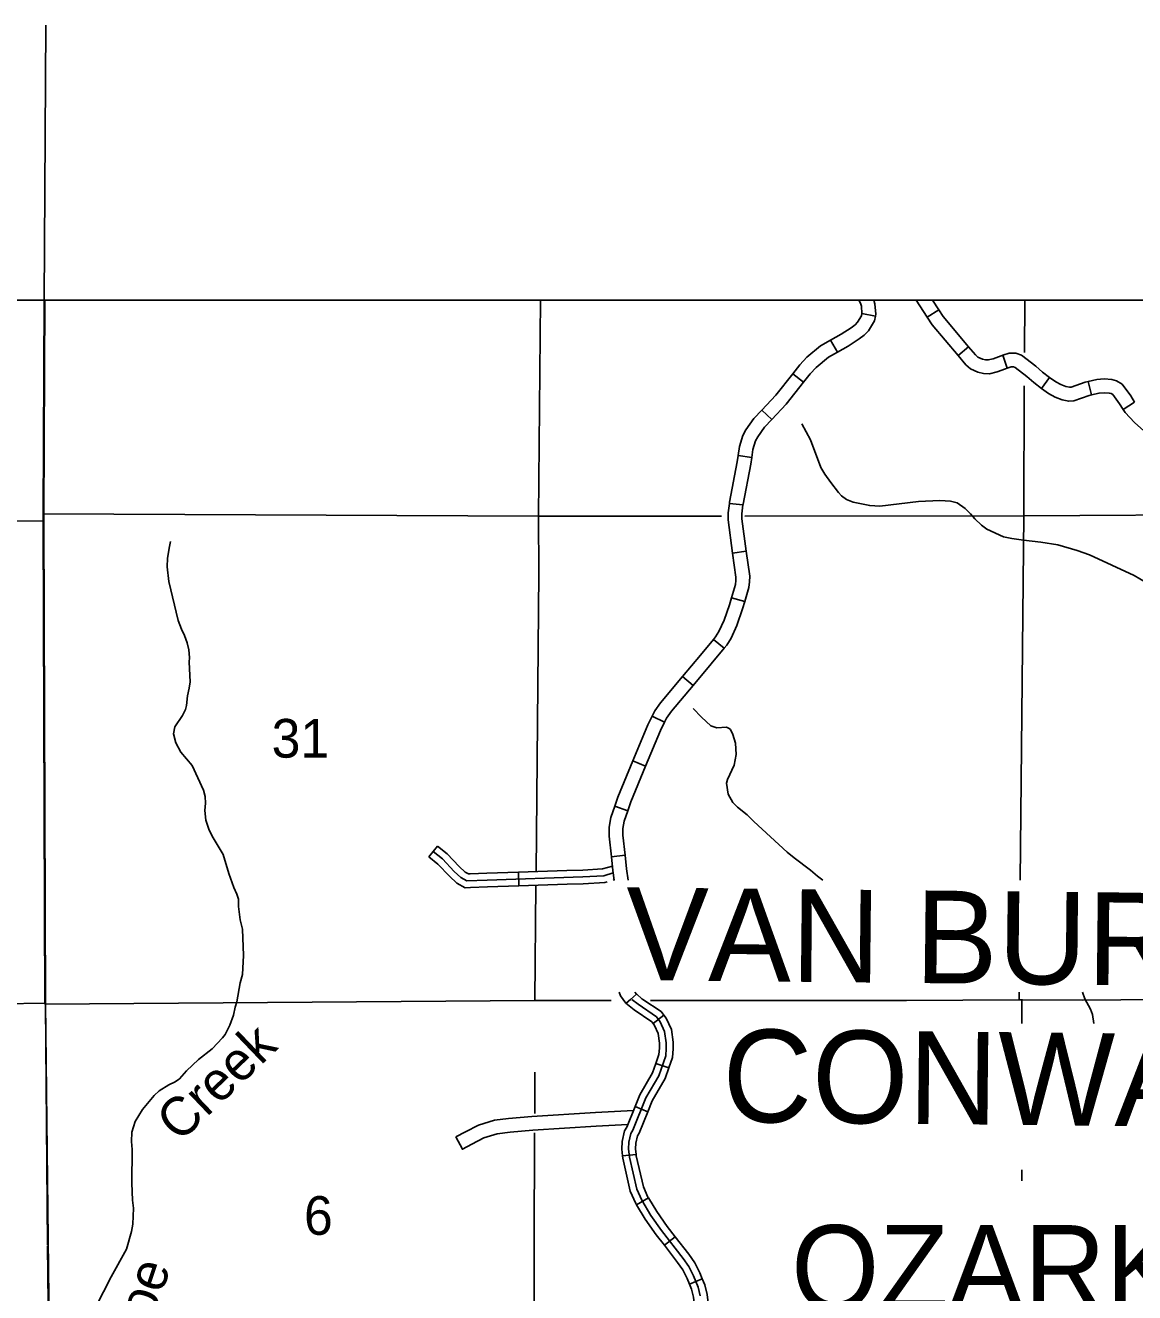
# Model space of a CAD drawing. Extents: x 1373862 to 1376999, y 1168398 to 1170455.
# Drawn here: x 1375555 to 1375797.1, y 1169362.9 to 1169639.4 of the extents above; entities that cross this region are included whole.
import ezdxf

# ---------------------------------------------------------------- set-up
doc = ezdxf.new("R2010")
doc.units = 0
for name, color, linetype in [('Level 2', 7, 'Continuous'), ('Level 32', 7, 'Continuous'), ('Level 35', 7, 'Continuous'), ('Level 4', 7, 'Continuous'), ('Level 45', 7, 'Continuous'), ('Level 46', 7, 'Continuous'), ('Level 5', 7, 'Continuous'), ('Level 8', 7, 'Continuous'), ('R_Dimension', 7, 'Continuous'), ('R_Draft', 7, 'Continuous')]:
    doc.layers.add(name, color=color, linetype=linetype)

msp = doc.modelspace()

# ---------------------------------------------------------------- linework, layer by layer
at = {"layer": 'Level 2'}
for points in [[(1375559.08, 1169579.43), (1375558.86, 1169532.82), (1375558.86, 1169531.1), (1375559.25, 1169425.84)], [(1375559.23, 1169579.43), (1375559.01, 1169532.99), (1375559, 1169531.27), (1375559.39, 1169426.01)], [(1375691.41, 1169426.65), (1375747.28, 1169426.64), (1375771.86, 1169426.75), (1375772.49, 1169426.76), (1375785.76, 1169426.72), (1375877.01, 1169427.47), (1375877.33, 1169427.47), (1375888.65, 1169427.27)], [(1375691.41, 1169426.65), (1375747.28, 1169426.64), (1375771.86, 1169426.75), (1375772.49, 1169426.76), (1375785.76, 1169426.72), (1375877.01, 1169427.47), (1375877.33, 1169427.47), (1375888.65, 1169427.27)], [(1375559.25, 1169425.84), (1375666.19, 1169426.66), (1375682.85, 1169426.66)], [(1375559.25, 1169425.84), (1375666.19, 1169426.66), (1375682.85, 1169426.66)], [(1375559.37, 1169425.84), (1375559.85, 1169373.34)], [(1375559.39, 1169426.01), (1375560.53, 1169323.17), (1375560.52, 1169321.29), (1375560.75, 1169303.22)], [(1375559.85, 1169373.12), (1375560.43, 1169323.13), (1375560.44, 1169321.15), (1375560.68, 1169300.07)]]:
    msp.add_lwpolyline(points, dxfattribs=at)
at = {"layer": 'Level 32'}
for p, q in [((1375751.81, 1169575.71), (1375754.32, 1169577.35)), ((1375737.56, 1169576.54), (1375740.5, 1169575.97)), ((1375730.69, 1169570.7), (1375732.18, 1169568.09)), ((1375758.54, 1169567.36), (1375760.83, 1169569.29)), ((1375769.21, 1169564.59), (1375768.3, 1169567.45)), ((1375722.44, 1169563.39), (1375724.8, 1169561.53)), ((1375776.7, 1169560.21), (1375778.49, 1169562.61)), ((1375787.64, 1169558.77), (1375786.94, 1169561.68)), ((1375715.68, 1169555.47), (1375717.85, 1169553.41)), ((1375794.53, 1169555.6), (1375797.06, 1169557.21)), ((1375710.52, 1169545.54), (1375713.49, 1169545.11)), ((1375708.62, 1169535.11), (1375711.59, 1169534.76)), ((1375709.33, 1169524.26), (1375712.31, 1169524.67)), ((1375709.08, 1169514.49), (1375711.97, 1169513.66)), ((1375705.16, 1169505.41), (1375707.48, 1169503.5)), ((1375698.41, 1169497.31), (1375700.7, 1169495.38)), ((1375691.77, 1169488.68), (1375694.47, 1169487.37)), ((1375687.58, 1169478.9), (1375690.35, 1169477.75)), ((1375683.61, 1169469.03), (1375686.44, 1169468.03)), ((1375682.88, 1169458.01), (1375685.86, 1169458.33)), ((1375687.02, 1169426.84), (1375688.38, 1169427.97)), ((1375686.08, 1169426.05), (1375687.02, 1169426.84)), ((1375691.98, 1169421.57), (1375694.35, 1169423.41)), ((1375692.59, 1169412.9), (1375695.42, 1169411.9)), ((1375688.03, 1169403.49), (1375690.81, 1169402.36)), ((1375685.29, 1169392.76), (1375688.28, 1169393.05)), ((1375688.38, 1169382.04), (1375690.94, 1169383.59)), ((1375694.45, 1169373.2), (1375696.82, 1169375.04)), ((1375699.94, 1169364.71), (1375702.71, 1169365.86))]:
    msp.add_line(p, q, dxfattribs=at)
for points in [[(1375736.88, 1169579.43), (1375737.21, 1169578.81), (1375737.42, 1169578.11), (1375737.56, 1169576.56), (1375737.56, 1169576.54)], [(1375740.16, 1169579.43), (1375740.38, 1169578.68), (1375740.59, 1169576.41), (1375740.5, 1169575.97)], [(1375749.37, 1169579.43), (1375751.81, 1169575.71)], [(1375752.96, 1169579.43), (1375754.32, 1169577.35)], [(1375754.32, 1169577.35), (1375755.28, 1169575.89), (1375760.83, 1169569.29)], [(1375737.56, 1169576.54), (1375737.46, 1169576.04), (1375736.6, 1169574.62), (1375736.08, 1169574.09), (1375735.21, 1169573.44), (1375732.98, 1169572.01), (1375730.69, 1169570.7)], [(1375740.5, 1169575.97), (1375740.3, 1169574.95), (1375738.98, 1169572.77), (1375738.06, 1169571.83), (1375736.93, 1169570.98), (1375734.54, 1169569.44), (1375732.18, 1169568.09)], [(1375751.81, 1169575.71), (1375752.87, 1169574.1), (1375758.54, 1169567.36)], [(1375730.69, 1169570.7), (1375728.52, 1169569.46), (1375725.5, 1169566.98), (1375723.98, 1169565.35), (1375722.44, 1169563.39)], [(1375760.83, 1169569.29), (1375762.34, 1169567.49), (1375762.87, 1169567.05), (1375763.84, 1169566.61), (1375764.52, 1169566.45), (1375765.1, 1169566.41), (1375766.15, 1169566.67), (1375767.92, 1169567.33), (1375768.3, 1169567.45)], [(1375732.18, 1169568.09), (1375730.23, 1169566.98), (1375727.56, 1169564.79), (1375726.26, 1169563.4), (1375724.8, 1169561.53)], [(1375758.54, 1169567.36), (1375760.22, 1169565.36), (1375761.26, 1169564.49), (1375762.85, 1169563.76), (1375764.08, 1169563.46), (1375765.38, 1169563.39), (1375767.03, 1169563.8), (1375768.9, 1169564.49), (1375769.21, 1169564.59)], [(1375768.3, 1169567.45), (1375769.69, 1169567.89), (1375771.16, 1169567.88), (1375772.39, 1169567.46), (1375775.49, 1169565.07), (1375776.93, 1169563.77), (1375778.49, 1169562.61)], [(1375722.44, 1169563.39), (1375718.75, 1169558.71), (1375715.68, 1169555.47)], [(1375769.21, 1169564.59), (1375770.14, 1169564.89), (1375770.65, 1169564.88), (1375770.96, 1169564.78), (1375773.56, 1169562.77), (1375775.03, 1169561.45), (1375776.7, 1169560.21)], [(1375724.8, 1169561.53), (1375721.02, 1169556.75), (1375717.85, 1169553.41)], [(1375776.7, 1169560.21), (1375778.24, 1169559.06), (1375779.69, 1169558.3), (1375781.21, 1169557.71), (1375782.69, 1169557.41), (1375783.8, 1169557.52), (1375787.12, 1169558.64), (1375787.64, 1169558.77)], [(1375778.49, 1169562.61), (1375779.85, 1169561.6), (1375780.93, 1169561.03), (1375782.05, 1169560.6), (1375782.85, 1169560.44), (1375783.17, 1169560.47), (1375786.28, 1169561.53), (1375786.94, 1169561.68)], [(1375786.94, 1169561.68), (1375788.8, 1169562.13), (1375790.37, 1169562.26), (1375792.05, 1169562.16), (1375793.13, 1169561.82), (1375794.32, 1169561.14), (1375796.21, 1169558.55), (1375797.06, 1169557.21)], [(1375787.64, 1169558.77), (1375789.28, 1169559.16), (1375790.4, 1169559.26), (1375791.5, 1169559.19), (1375791.93, 1169559.05), (1375792.28, 1169558.85), (1375793.73, 1169556.86), (1375794.53, 1169555.6)], [(1375715.68, 1169555.47), (1375713.93, 1169553.64), (1375712.24, 1169551.18), (1375711.56, 1169549.92), (1375710.8, 1169547.52), (1375710.52, 1169545.54)], [(1375794.53, 1169555.6), (1375794.96, 1169554.92), (1375797.02, 1169552.74), (1375799.04, 1169550.97), (1375800.09, 1169550.26), (1375802.16, 1169549.15), (1375803.59, 1169548.71)], [(1375717.85, 1169553.41), (1375716.27, 1169551.75), (1375714.8, 1169549.62), (1375714.34, 1169548.75), (1375713.74, 1169546.85), (1375713.49, 1169545.11)], [(1375710.52, 1169545.54), (1375710.32, 1169544.16), (1375708.65, 1169535.37), (1375708.62, 1169535.11)], [(1375713.49, 1169545.11), (1375713.28, 1169543.67), (1375711.61, 1169534.91), (1375711.59, 1169534.76)], [(1375708.62, 1169535.11), (1375708.37, 1169533.06), (1375708.34, 1169531.53), (1375709.33, 1169524.26)], [(1375711.59, 1169534.76), (1375711.37, 1169532.85), (1375711.34, 1169531.7), (1375712.31, 1169524.67)], [(1375709.33, 1169524.26), (1375710.05, 1169519.02), (1375710.04, 1169518.25), (1375709.92, 1169517.42), (1375709.08, 1169514.49)], [(1375712.31, 1169524.67), (1375713.05, 1169519.21), (1375713.04, 1169518.01), (1375712.86, 1169516.78), (1375711.97, 1169513.66)], [(1375709.08, 1169514.49), (1375708.65, 1169512.99), (1375707.48, 1169509.59), (1375706.35, 1169507.13), (1375705.62, 1169505.96), (1375705.16, 1169505.41)], [(1375711.97, 1169513.66), (1375711.51, 1169512.08), (1375710.26, 1169508.47), (1375708.99, 1169505.7), (1375708.06, 1169504.2), (1375707.48, 1169503.5)], [(1375705.16, 1169505.41), (1375702.33, 1169501.98), (1375698.41, 1169497.31)], [(1375707.48, 1169503.5), (1375704.64, 1169500.06), (1375700.7, 1169495.38)], [(1375698.41, 1169497.31), (1375693.61, 1169491.61), (1375692.32, 1169489.81), (1375691.77, 1169488.68)], [(1375700.7, 1169495.38), (1375695.98, 1169489.77), (1375694.9, 1169488.27), (1375694.47, 1169487.37)], [(1375691.77, 1169488.68), (1375690.84, 1169486.78), (1375687.58, 1169478.9)], [(1375694.47, 1169487.37), (1375693.58, 1169485.55), (1375690.35, 1169477.75)], [(1375687.58, 1169478.9), (1375684.31, 1169471.02), (1375683.61, 1169469.03)], [(1375690.35, 1169477.75), (1375687.12, 1169469.95), (1375686.44, 1169468.03)], [(1375683.61, 1169469.03), (1375682.73, 1169466.54), (1375682.39, 1169464.42), (1375682.4, 1169462.52), (1375682.88, 1169458.01)], [(1375686.44, 1169468.03), (1375685.65, 1169465.79), (1375685.39, 1169464.19), (1375685.4, 1169462.69), (1375685.86, 1169458.33)], [(1375682.88, 1169458.01), (1375683.2, 1169454.99)], [(1375685.86, 1169458.33), (1375686.18, 1169455.35), (1375686.51, 1169452.89)], [(1375683.2, 1169454.99), (1375683.48, 1169452.89)], [(1375684.56, 1169428.47), (1375684.86, 1169427.63), (1375685.43, 1169426.82)], [(1375687.96, 1169428.47), (1375688.38, 1169427.97)], [(1375688.39, 1169427.98), (1375689.55, 1169426.98), (1375689.75, 1169426.84)], [(1375691.98, 1169421.57), (1375691.67, 1169421.97), (1375687.82, 1169424.6), (1375686.05, 1169426.07), (1375685.43, 1169426.81)], [(1375686.08, 1169426.05), (1375686.05, 1169426.07), (1375685.43, 1169426.81)], [(1375694.82, 1169416.16), (1375694.85, 1169417.4), (1375694.49, 1169419.87), (1375693.55, 1169421.96), (1375692.69, 1169423.06), (1375688.68, 1169425.79), (1375687.33, 1169426.84)], [(1375694.35, 1169423.41), (1375693.75, 1169424.19), (1375689.73, 1169426.84)], [(1375695.42, 1169411.9), (1375696.23, 1169414.21), (1375696.35, 1169416.1), (1375696.38, 1169417.5), (1375695.97, 1169420.3), (1375694.86, 1169422.76), (1375694.35, 1169423.41)], [(1375692.59, 1169412.9), (1375693.26, 1169414.81), (1375693.35, 1169416.22), (1375693.37, 1169417.31), (1375693.06, 1169419.45), (1375692.27, 1169421.2), (1375691.98, 1169421.57)], [(1375702.26, 1169362.17), (1375701.79, 1169364.1), (1375700.76, 1169366.57), (1375699.75, 1169368.58), (1375698.52, 1169370.34), (1375693.84, 1169376.4), (1375691.48, 1169379.74), (1375689.5, 1169383.02), (1375688.4, 1169385.46), (1375686.8, 1169392.47), (1375686.63, 1169394.23), (1375686.7, 1169395.68), (1375687.13, 1169397.63), (1375687.54, 1169398.36), (1375690.41, 1169405.42), (1375693.21, 1169410.22), (1375694.72, 1169414.52), (1375694.82, 1169416.16)], [(1375688.03, 1169403.49), (1375689.08, 1169406.07), (1375691.87, 1169410.84), (1375692.59, 1169412.9)], [(1375690.81, 1169402.36), (1375691.78, 1169404.75), (1375694.6, 1169409.58), (1375695.42, 1169411.9)], [(1375685.29, 1169392.76), (1375685.15, 1169394.2), (1375685.24, 1169395.88), (1375685.74, 1169398.16), (1375686.21, 1169399), (1375688.03, 1169403.49)], [(1375688.28, 1169393.05), (1375688.16, 1169394.27), (1375688.22, 1169395.47), (1375688.58, 1169397.08), (1375688.92, 1169397.69), (1375690.81, 1169402.36)], [(1375688.38, 1169382.04), (1375688.2, 1169382.33), (1375687, 1169384.99), (1375685.34, 1169392.24), (1375685.29, 1169392.76)], [(1375690.94, 1169383.59), (1375690.86, 1169383.73), (1375689.86, 1169385.95), (1375688.31, 1169392.72), (1375688.28, 1169393.05)], [(1375696.82, 1169375.04), (1375695.07, 1169377.3), (1375692.76, 1169380.58), (1375690.94, 1169383.59)], [(1375694.45, 1169373.2), (1375692.66, 1169375.52), (1375690.25, 1169378.94), (1375688.38, 1169382.04)], [(1375702.71, 1169365.86), (1375702.15, 1169367.21), (1375701.06, 1169369.37), (1375699.75, 1169371.25), (1375696.82, 1169375.04)], [(1375699.94, 1169364.71), (1375699.42, 1169365.96), (1375698.48, 1169367.82), (1375697.33, 1169369.47), (1375694.45, 1169373.2)], [(1375701.63, 1169354.74), (1375700.81, 1169361.91), (1375700.38, 1169363.64), (1375699.94, 1169364.71)], [(1375704.61, 1169355.09), (1375703.77, 1169362.44), (1375703.24, 1169364.58), (1375702.71, 1169365.86)]]:
    msp.add_lwpolyline(points, dxfattribs=at)
at = {"layer": 'Level 35'}
for points in [[(1375724.45, 1169552.46), (1375726.34, 1169548.96), (1375728.61, 1169542.97), (1375729.47, 1169541.47), (1375730.73, 1169539.66), (1375732.43, 1169537.45), (1375733.1, 1169536.73), (1375734.17, 1169535.96), (1375735.63, 1169535.35), (1375739.25, 1169534.64), (1375741.45, 1169534.48), (1375749.86, 1169535.5), (1375754.51, 1169535.76), (1375756.84, 1169535.61), (1375758.32, 1169535.2), (1375760.08, 1169533.97), (1375761.25, 1169532.82), (1375762.18, 1169531.74), (1375763.66, 1169530.33), (1375764.81, 1169529.46), (1375768.45, 1169527.83), (1375770.23, 1169527.45), (1375772.82, 1169527.05), (1375776.61, 1169526.64), (1375780.33, 1169526.03), (1375784.51, 1169524.81), (1375787.2, 1169523.85), (1375796.92, 1169519.37), (1375805.64, 1169514.27)], [(1375586.68, 1169526.81), (1375586.43, 1169525.7), (1375585.99, 1169523.13), (1375585.94, 1169521.27), (1375586.31, 1169518.04), (1375588.33, 1169509.54), (1375589.07, 1169507.64), (1375589.74, 1169506.24), (1375590.3, 1169504.66), (1375590.63, 1169503.18), (1375590.78, 1169501.5), (1375590.73, 1169500.44), (1375590.93, 1169496.15), (1375590.76, 1169494.8), (1375590.38, 1169493.11), (1375590.15, 1169491.03), (1375589.94, 1169490.1), (1375589.31, 1169488.79), (1375587.61, 1169486.31), (1375587.34, 1169484.84), (1375587.86, 1169482.88), (1375588.94, 1169480.81), (1375591.41, 1169477.9), (1375593.84, 1169472.49), (1375594.25, 1169471.11), (1375594.33, 1169469.67), (1375594.18, 1169468.1), (1375594.36, 1169465.96), (1375595, 1169464.02), (1375595.75, 1169462.5), (1375598.15, 1169458.52), (1375599.41, 1169454.36), (1375600.48, 1169451.28), (1375601.17, 1169449.82), (1375601.52, 1169448.72), (1375601.52, 1169447.16), (1375601.9, 1169444.25), (1375602.36, 1169442.21), (1375602.59, 1169436.44), (1375602.39, 1169432.27), (1375601.9, 1169430.46), (1375601.16, 1169426.32)], [(1375700.71, 1169490.32), (1375702.53, 1169488.49), (1375704.59, 1169486.59), (1375705.9, 1169486.12), (1375708.02, 1169486.26), (1375708.58, 1169486), (1375708.89, 1169485.74), (1375709.38, 1169484.65), (1375709.97, 1169482.79), (1375710.1, 1169480.34), (1375709.68, 1169477.95), (1375708.2, 1169474.83), (1375707.97, 1169474.03), (1375708.33, 1169471.66), (1375709.34, 1169469.85), (1375710.42, 1169468.8), (1375712.49, 1169467.15), (1375713.99, 1169465.7), (1375721.2, 1169459.01), (1375722.76, 1169457.74), (1375726.35, 1169455.06), (1375727.82, 1169453.77), (1375728.98, 1169452.89)], [(1375785.66, 1169428.47), (1375786.21, 1169426.97)], [(1375601.16, 1169426.32), (1375600.78, 1169425.15), (1375600.4, 1169423.39), (1375599.62, 1169421.23), (1375598.57, 1169419.24), (1375598.04, 1169418.49), (1375595.73, 1169416.06)], [(1375786.21, 1169426.97), (1375787.42, 1169424.72), (1375787.85, 1169423.6), (1375788.14, 1169421.63)], [(1375595.73, 1169416.06), (1375592.8, 1169413.72), (1375590.17, 1169411.29), (1375588.62, 1169409.54), (1375587.69, 1169408.88), (1375586.32, 1169408.19), (1375584.16, 1169406.88), (1375583.13, 1169405.9), (1375580.52, 1169402.84), (1375578.96, 1169400.23), (1375578.2, 1169397.91), (1375578.13, 1169395.89), (1375578.3, 1169394.11), (1375578.25, 1169386.79), (1375578.39, 1169383.08), (1375578.58, 1169381.34), (1375578.42, 1169377.79), (1375578.18, 1169376.22), (1375577.03, 1169372.34), (1375573.72, 1169366.31)], [(1375573.72, 1169366.31), (1375570.34, 1169359.74), (1375569.96, 1169358.65), (1375569.51, 1169356.05), (1375569.2, 1169351.25), (1375568.31, 1169346.75), (1375567.31, 1169343.32), (1375565.98, 1169340.89), (1375565.35, 1169340.35), (1375564.47, 1169339.95), (1375563.1, 1169339.62), (1375561.03, 1169339.55), (1375560.24, 1169339.61)]]:
    msp.add_lwpolyline(points, dxfattribs=at)
at = {"layer": 'Level 4'}
msp.add_lwpolyline([(1375481.04, 1169425.5), (1375540.28, 1169425.73), (1375559.39, 1169426.01)], dxfattribs=at)
at = {"layer": 'Level 45'}
for p, q in [((1375643.06, 1169457.97), (1375644.93, 1169460.32)), ((1375662.7, 1169451.64), (1375662.6, 1169454.64))]:
    msp.add_line(p, q, dxfattribs=at)
for points in [[(1375643.06, 1169457.97), (1375645.03, 1169456.41), (1375647.54, 1169453.73), (1375649.17, 1169452.2), (1375650.99, 1169451.23), (1375652.15, 1169451.27)], [(1375644, 1169459.14), (1375646.04, 1169457.52), (1375648.6, 1169454.79), (1375650.05, 1169453.43), (1375651.33, 1169452.74), (1375655.77, 1169452.91), (1375676.67, 1169453.6), (1375681.2, 1169453.85), (1375683.25, 1169454.46)], [(1375644.93, 1169460.32), (1375647.06, 1169458.63), (1375649.67, 1169455.85), (1375650.94, 1169454.65), (1375651.68, 1169454.26), (1375652.04, 1169454.27)], [(1375662.6, 1169454.64), (1375673.15, 1169454.98)], [(1375673.15, 1169454.98), (1375676.61, 1169455.09), (1375680.94, 1169455.34), (1375683.09, 1169455.97)], [(1375652.04, 1169454.27), (1375655.72, 1169454.41), (1375662.6, 1169454.64)], [(1375673.25, 1169451.98), (1375676.74, 1169452.1), (1375681.45, 1169452.36), (1375681.92, 1169452.5)], [(1375683.25, 1169452.89), (1375683.47, 1169452.96)], [(1375652.15, 1169451.27), (1375655.82, 1169451.41), (1375662.7, 1169451.64)], [(1375662.7, 1169451.64), (1375673.25, 1169451.98)]]:
    msp.add_lwpolyline(points, dxfattribs=at)
at = {"layer": 'Level 46'}
for points in [[(1375687.68, 1169402.62), (1375679.38, 1169402.17), (1375665.54, 1169401.29), (1375660.45, 1169400.84), (1375657.35, 1169400.5), (1375653.91, 1169399.43), (1375651.04, 1169397.94), (1375648.95, 1169396.84)], [(1375686.43, 1169399.55), (1375679.56, 1169399.17), (1375665.76, 1169398.3), (1375660.75, 1169397.86), (1375657.97, 1169397.55), (1375655.05, 1169396.64), (1375652.43, 1169395.28), (1375650.35, 1169394.18), (1375648.95, 1169396.84)]]:
    msp.add_lwpolyline(points, dxfattribs=at)
at = {"layer": 'Level 5'}
for points in [[(1375667.44, 1169579.43), (1375666.94, 1169532.32)], [(1375773.07, 1169579.43), (1375773.01, 1169568.02)], [(1375772.98, 1169560.78), (1375772.84, 1169532.39)], [(1375666.94, 1169532.32), (1375558.86, 1169532.82)], [(1375706.92, 1169532.34), (1375666.94, 1169532.32)], [(1375772.84, 1169532.39), (1375712.01, 1169532.35)], [(1375772.84, 1169532.39), (1375772.1, 1169452.89)], [(1375870.52, 1169532.96), (1375772.84, 1169532.39)], [(1375559, 1169531.27), (1375505.39, 1169530.93)], [(1375666.94, 1169532.32), (1375667.02, 1169519.79), (1375666.44, 1169454.76)], [(1375666.41, 1169451.76), (1375666.19, 1169426.66)], [(1375771.88, 1169428.47), (1375771.86, 1169426.75)], [(1375772.47, 1169421.63), (1375772.47, 1169426.88)], [(1375666.18, 1169410.96), (1375666.15, 1169401.93)], [(1375666.13, 1169397.77), (1375665.93, 1169348.48)], [(1375772.43, 1169387.28), (1375772.44, 1169389.67)]]:
    msp.add_lwpolyline(points, dxfattribs=at)
at = {"layer": 'R_Dimension'}
msp.add_line((1375559.49, 1169639.43), (1375559.08, 1169579.43), dxfattribs=at)
at = {"layer": 'R_Draft'}
msp.add_lwpolyline([(1374675.34, 1169579.43), (1376182.76, 1169579.43), (1376182.76, 1168562.99), (1374675.34, 1168562.99)], close=True, dxfattribs=at)

# ---------------------------------------------------------------- texts
at = {"layer": 'Level 35'}
for s, rotation, p in [('Creek', 43.7314, (1375588.65, 1169395.44)), ('Poe', 71.354, (1375580.37, 1169349.44))]:
    msp.add_text(s, height=8.44, rotation=rotation, dxfattribs=at).set_placement(p)
at = {"layer": 'Level 5'}
for s, height, p in [('31', 8.448, (1375608.73, 1169479.62)), ('6', 8.44, (1375615.8, 1169375.49))]:
    msp.add_text(s, height=height, dxfattribs=at).set_placement(p)
at = {"layer": 'Level 8'}
msp.add_text('OZARK', height=18.48, dxfattribs=at).set_placement((1375722.11, 1169359.13))
at = {"layer": 'R_Draft'}
for s, p in [('VAN BUREN COUNTY', (1375685.95, 1169431.1)), ('CONWAY COUNTY', (1375707.05, 1169400.15))]:
    msp.add_text(s, height=20.2145, rotation=359.4022, dxfattribs=at).set_placement(p)

doc.saveas('drawing.dxf')
